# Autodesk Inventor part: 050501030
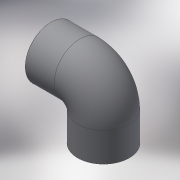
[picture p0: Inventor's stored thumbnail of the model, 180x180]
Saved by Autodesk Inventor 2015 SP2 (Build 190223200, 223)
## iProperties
Created: 2017-10
Part Number: 050501030
Material: Generic
Description: PLASSON THREADED 90° ELBOW PVC 3"
Document SubType Name: Modeling
Designer: KIM
Density: 1 g/cm^3
Appearance: Default
Author: KIM
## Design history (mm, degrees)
derived "050501.ipt"
feature "Solid1::050501.ipt"
tag "TaggingFeature1"
body "Solid1"
other parameters: "d7" = 0.84926, "d9" = 108, "d13" = 90 deg, "d19" = 90 deg, "d20" = 84.926, "d21" = 33, "d22" = 0, "d24" = 90 deg, "d26" = 76.4334, "d27" = 90 deg, "d28" = 33, "G_" = 84.926, "E_" = 108, "H_" = 154, "lt_" = 33
